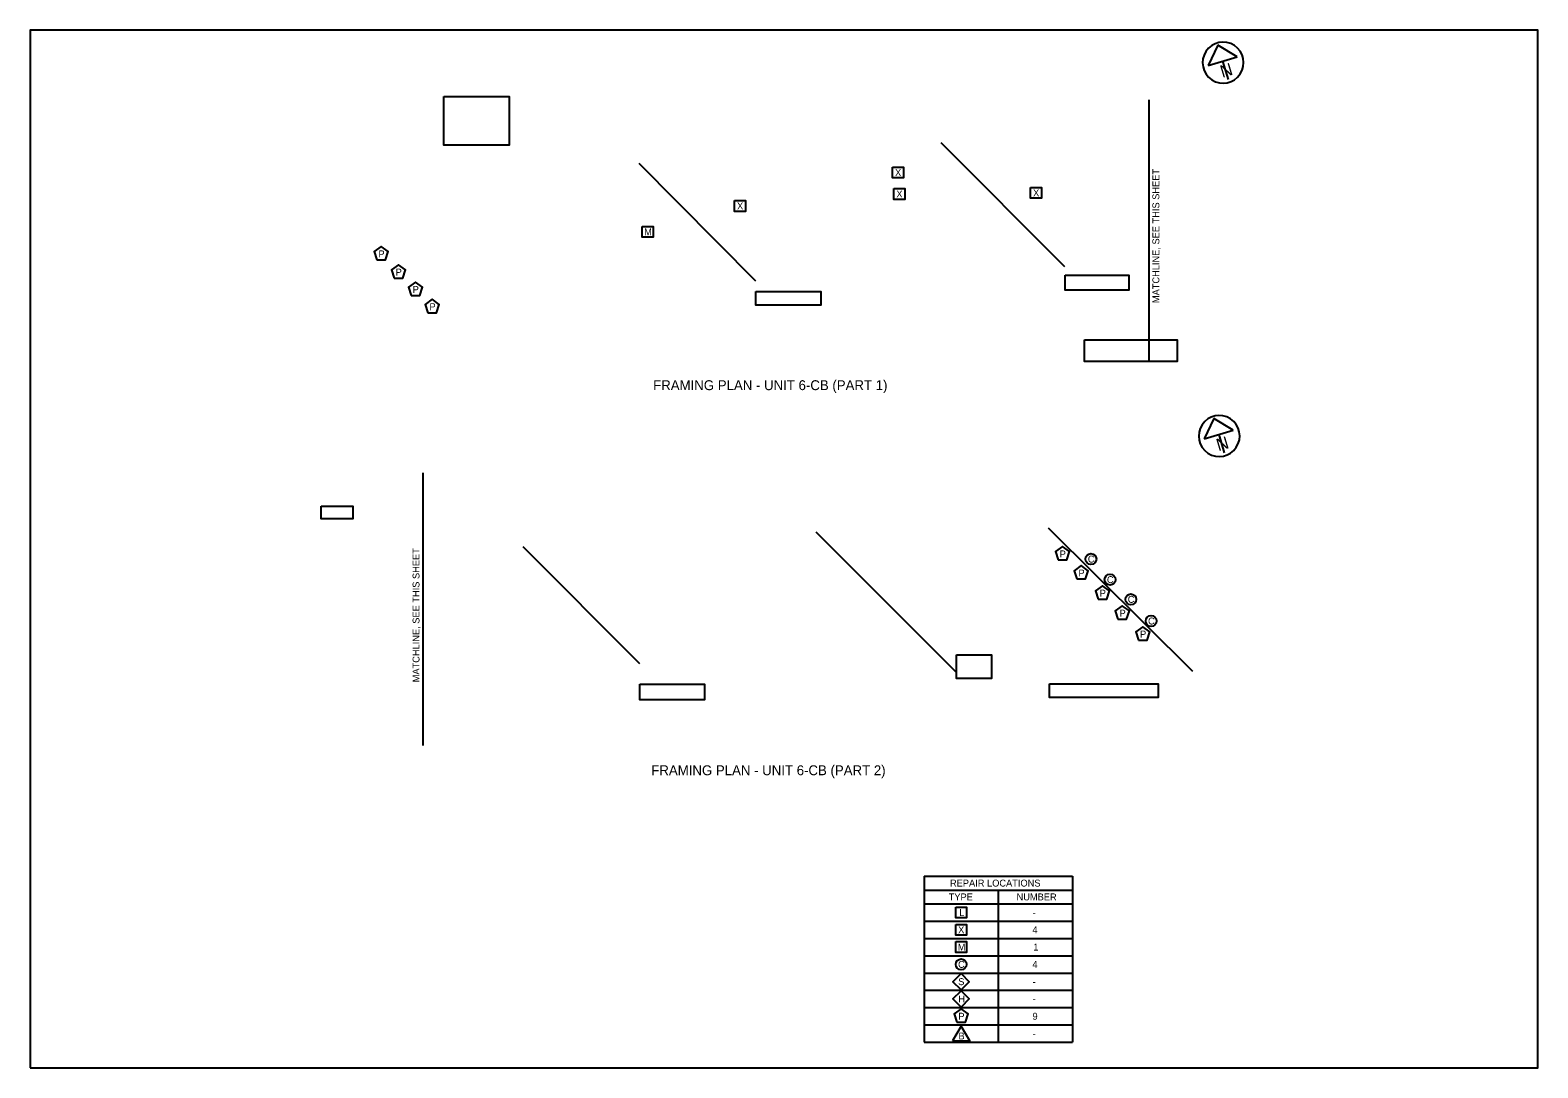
# Model space of a CAD drawing. Extents: x 100 to 130.5, y 100 to 121.
import ezdxf

# ---------------------------------------------------------------- set-up
doc = ezdxf.new("R2010")
doc.units = 0
for name, color, linetype in [('BR_P_Gen_Text', 7, 'Continuous'), ('BR_X_Sub_Centerline', 7, 'Continuous'), ('BR_X_Sub_Text', 7, 'Continuous'), ('SC_Scratch1', 7, 'Continuous'), ('SH_Data', 7, 'Continuous'), ('SH_Masking', 7, 'Continuous')]:
    doc.layers.add(name, color=color, linetype=linetype)

msp = doc.modelspace()

# ---------------------------------------------------------------- linework, layer by layer
at = {"layer": 'BR_P_Gen_Text'}
for p, q in [((122.633, 119.592), (122.633, 114.315)), ((107.946, 112.038), (107.946, 106.522)), ((118.083, 103.879), (118.083, 100.519)), ((118.083, 103.879), (121.083, 103.879)), ((121.083, 103.879), (121.083, 100.519)), ((118.083, 103.599), (121.083, 103.599)), ((119.583, 103.599), (119.583, 100.519)), ((118.083, 103.319), (121.083, 103.319)), ((118.083, 102.969), (121.083, 102.969)), ((118.083, 102.619), (121.083, 102.619)), ((118.083, 102.269), (121.083, 102.269)), ((118.083, 101.919), (121.083, 101.919)), ((118.083, 101.569), (121.083, 101.569)), ((118.083, 101.219), (121.083, 101.219)), ((118.083, 100.869), (121.083, 100.869)), ((118.083, 100.519), (121.083, 100.519))]:
    msp.add_line(p, q, dxfattribs=at)
for points in [[(117.448, 118.228), (117.668, 118.228), (117.668, 118.008), (117.448, 118.008)], [(117.473, 117.794), (117.693, 117.794), (117.693, 117.574), (117.473, 117.574)], [(120.239, 117.817), (120.459, 117.817), (120.459, 117.597), (120.239, 117.597)], [(114.251, 117.553), (114.471, 117.553), (114.471, 117.333), (114.251, 117.333)], [(112.381, 117.028), (112.601, 117.028), (112.601, 116.808), (112.381, 116.808)], [(107.014, 116.351), (107.191, 116.351), (107.245, 116.519), (107.102, 116.622), (106.96, 116.519)], [(107.361, 115.981), (107.538, 115.981), (107.592, 116.149), (107.449, 116.253), (107.307, 116.149)], [(107.706, 115.63), (107.883, 115.63), (107.937, 115.798), (107.795, 115.902), (107.652, 115.798)], [(108.046, 115.281), (108.222, 115.281), (108.277, 115.449), (108.134, 115.553), (107.992, 115.449)], [(120.796, 110.279), (120.972, 110.279), (121.027, 110.447), (120.884, 110.55), (120.742, 110.447)], [(121.175, 109.893), (121.351, 109.893), (121.406, 110.06), (121.263, 110.164), (121.121, 110.06)], [(121.605, 109.484), (121.781, 109.484), (121.836, 109.652), (121.693, 109.756), (121.551, 109.652)], [(122.006, 109.079), (122.182, 109.079), (122.237, 109.247), (122.094, 109.351), (121.951, 109.247)], [(122.421, 108.657), (122.598, 108.657), (122.652, 108.824), (122.51, 108.928), (122.367, 108.824)], [(118.723, 103.254), (118.943, 103.254), (118.943, 103.034), (118.723, 103.034)], [(118.723, 102.904), (118.943, 102.904), (118.943, 102.684), (118.723, 102.684)], [(118.723, 102.554), (118.943, 102.554), (118.943, 102.334), (118.723, 102.334)], [(118.833, 101.909), (118.998, 101.744), (118.833, 101.579), (118.668, 101.744)], [(118.833, 101.559), (118.998, 101.394), (118.833, 101.229), (118.668, 101.394)], [(118.745, 100.923), (118.922, 100.923), (118.976, 101.091), (118.833, 101.194), (118.691, 101.091)], [(118.66, 100.544), (119.007, 100.544), (118.833, 100.844)]]:
    msp.add_lwpolyline(points, close=True, dxfattribs=at)
for centre in [(121.459, 110.296), (121.846, 109.88), (122.267, 109.481), (122.677, 109.043), (118.833, 102.094)]:
    msp.add_circle(centre, 0.11, dxfattribs=at)
at = {"layer": 'BR_X_Sub_Centerline'}
for p, q in [((120.931, 116.209), (118.431, 118.721)), ((112.311, 118.307), (114.671, 115.929)), ((118.738, 107.999), (115.898, 110.842)), ((123.518, 108.019), (120.603, 110.924)), ((112.336, 108.179), (109.975, 110.542))]:
    msp.add_line(p, q, dxfattribs=at)
at = {"layer": 'BR_X_Sub_Text'}
for points in [[(120.938, 116.04), (122.223, 116.04), (122.223, 115.739), (120.938, 115.739)], [(114.682, 115.71), (115.998, 115.71), (115.998, 115.432), (114.682, 115.432)], [(118.737, 108.361), (119.448, 108.361), (119.448, 107.878), (118.737, 107.878)], [(112.335, 107.765), (113.643, 107.765), (113.643, 107.448), (112.335, 107.448)], [(120.619, 107.773), (122.82, 107.773), (122.82, 107.492), (120.619, 107.492)]]:
    msp.add_lwpolyline(points, close=True, dxfattribs=at)
at = {"layer": 'SC_Scratch1'}
msp.add_lwpolyline([(100, 100), (130.5, 100), (130.5, 121), (100, 121)], close=True, dxfattribs=at)
at = {"layer": 'SH_Data'}
for p, q in [((124.025, 120.699), (123.83, 120.284)), ((124.418, 120.462), (124.025, 120.699)), ((123.83, 120.284), (124.418, 120.462)), ((124.124, 120.373), (124.236, 120.003)), ((123.946, 113.143), (123.75, 112.728)), ((123.75, 112.728), (124.339, 112.906)), ((124.339, 112.906), (123.946, 113.143)), ((124.045, 112.817), (124.157, 112.447))]:
    msp.add_line(p, q, dxfattribs=at)
for centre in [(124.133, 120.342), (124.054, 112.786)]:
    msp.add_arc(centre, 0.415, 146.6201, 146.6036, dxfattribs=at)
at = {"layer": 'SH_Masking'}
for points in [[(108.367, 119.657), (109.687, 119.657), (109.687, 118.671), (108.367, 118.671)], [(121.328, 114.73), (123.201, 114.73), (123.201, 114.296), (121.328, 114.296)], [(105.884, 111.368), (106.527, 111.368), (106.527, 111.108), (105.884, 111.108)]]:
    msp.add_lwpolyline(points, close=True, dxfattribs=at)

# ---------------------------------------------------------------- texts
at = {"layer": 'BR_P_Gen_Text'}
for s, height, p in [('X', 0.14, (117.497, 118.048)), ('X', 0.14, (117.523, 117.614)), ('X', 0.14, (120.289, 117.637)), ('X', 0.14, (114.3, 117.373)), ('M', 0.14, (112.422, 116.848)), ('P', 0.14, (107.046, 116.402)), ('P', 0.14, (107.393, 116.033)), ('P', 0.14, (107.738, 115.682)), ('P', 0.14, (108.078, 115.333)), ('FRAMING PLAN - UNIT 6-CB (PART 1)', 0.2, (112.603, 113.715)), ('P', 0.14, (120.828, 110.33)), ('C', 0.14, (121.396, 110.226)), ('P', 0.14, (121.207, 109.944)), ('C', 0.14, (121.783, 109.81)), ('P', 0.14, (121.637, 109.536)), ('C', 0.14, (122.204, 109.411)), ('P', 0.14, (122.038, 109.131)), ('C', 0.14, (122.614, 108.973)), ('P', 0.14, (122.453, 108.708)), ('FRAMING PLAN - UNIT 6-CB (PART 2)', 0.2, (112.565, 105.922)), ('REPAIR LOCATIONS', 0.14, (118.608, 103.669)), ('TYPE', 0.14, (118.582, 103.389)), ('NUMBER', 0.14, (119.955, 103.389)), ('L', 0.14, (118.795, 103.074)), ('-', 0.14, (120.28, 103.074)), ('X', 0.14, (118.773, 102.724)), ('4', 0.14, (120.275, 102.724)), ('M', 0.14, (118.765, 102.374)), ('1', 0.14, (120.294, 102.374)), ('C', 0.14, (118.771, 102.024)), ('4', 0.14, (120.275, 102.024)), ('S', 0.14, (118.775, 101.674)), ('-', 0.14, (120.28, 101.674)), ('H', 0.14, (118.777, 101.324)), ('-', 0.14, (120.28, 101.324)), ('P', 0.14, (118.777, 100.974)), ('9', 0.14, (120.277, 100.974)), ('B', 0.14, (118.779, 100.574)), ('-', 0.14, (120.28, 100.624))]:
    msp.add_text(s, height=height, dxfattribs=at).set_placement(p)
for p in [(122.843, 115.476), (107.876, 107.802)]:
    msp.add_text('MATCHLINE, SEE THIS SHEET', height=0.14, rotation=90, dxfattribs=at).set_placement(p)
at = {"layer": 'SH_Data'}
for p in [(124.118, 120.033), (124.039, 112.477)]:
    msp.add_text('N', height=0.25, rotation=16.8403, dxfattribs=at).set_placement(p)

doc.saveas('drawing.dxf')
